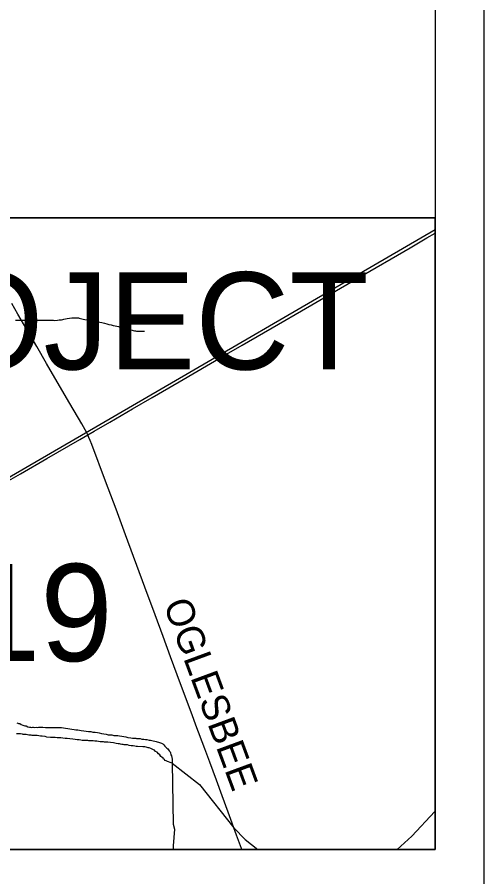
# Model space of a CAD drawing. Extents: x -19.5 to 44.1, y 0 to 22.
# Drawn here: x 8.541 to 9.5, y 17.841 to 19.61 of the extents above; entities that cross this region are included whole.
import ezdxf

# ---------------------------------------------------------------- set-up
doc = ezdxf.new("R2010")
doc.units = 0
for name, color, linetype in [('GM_X_County_Road', 7, 'Continuous'), ('GM_X_Minor_River', 7, 'Continuous'), ('GM_X_Township', 7, 'Continuous'), ('GM_X_Township_Road', 7, 'Continuous'), ('GM_X_Township_Road_Text', 7, 'Continuous'), ('SH_Data', 7, 'Continuous'), ('SH_Masking', 7, 'Continuous'), ('SH_Text', 7, 'Continuous')]:
    doc.layers.add(name, color=color, linetype=linetype)

msp = doc.modelspace()

# ---------------------------------------------------------------- linework, layer by layer
at = {"layer": 'GM_X_County_Road'}
for points in [[(8.6863, 18.7507), (8.6991, 18.7582), (8.7313, 18.777), (8.7781, 18.804), (8.8184, 18.8275), (8.8738, 18.8595), (8.9382, 18.8972), (8.9666, 18.9138), (9.0038, 18.9352), (9.0778, 18.9784), (9.1252, 19.0058), (9.1842, 19.0402), (9.2396, 19.0723), (9.3487, 19.1356), (9.383, 19.1556), (9.4, 19.1655)], [(8.5099, 18.6484), (8.5481, 18.6706), (8.6019, 18.7016), (8.6696, 18.7409), (8.6863, 18.7507)]]:
    msp.add_lwpolyline(points, dxfattribs=at)
at = {"layer": 'GM_X_Minor_River'}
for points in [[(8.5376, 18.9864), (8.5418, 18.9863), (8.5464, 18.9862), (8.5509, 18.9862), (8.5555, 18.9865), (8.5604, 18.9864), (8.5669, 18.9866), (8.5711, 18.9866), (8.5757, 18.9865), (8.5799, 18.9868), (8.5841, 18.9867), (8.5974, 18.9865), (8.6016, 18.9864), (8.6058, 18.9863), (8.6096, 18.9863), (8.6134, 18.9862), (8.616, 18.9862), (8.6183, 18.9861), (8.624, 18.9868), (8.6275, 18.9871), (8.6301, 18.9871), (8.6324, 18.9874), (8.6351, 18.9881), (8.637, 18.9885), (8.6401, 18.9892), (8.6439, 18.9899), (8.6485, 18.9906), (8.6531, 18.9912), (8.6569, 18.9912), (8.6599, 18.9915), (8.6622, 18.9915), (8.6641, 18.991), (8.6668, 18.991), (8.6687, 18.9906), (8.6713, 18.9902), (8.674, 18.9894), (8.677, 18.9889), (8.6804, 18.9881)], [(8.6804, 18.9881), (8.6842, 18.9873), (8.6876, 18.9868), (8.691, 18.986), (8.6948, 18.9852), (8.699, 18.9844), (8.715, 18.9814), (8.7203, 18.9802), (8.7252, 18.979), (8.7298, 18.9778), (8.7343, 18.9769), (8.7385, 18.9757), (8.7427, 18.9749), (8.7461, 18.9741), (8.7491, 18.9732), (8.7521, 18.9721), (8.7567, 18.9712), (8.7593, 18.9704), (8.7616, 18.97), (8.7635, 18.97), (8.7658, 18.9688), (8.7699, 18.9676), (8.7726, 18.9671), (8.7749, 18.9667), (8.7775, 18.9659), (8.7798, 18.9651), (8.7825, 18.9647), (8.7844, 18.9643), (8.7866, 18.9642), (8.7889, 18.9642), (8.792, 18.9642), (8.795, 18.9637), (8.7973, 18.9637), (8.7996, 18.9636), (8.8015, 18.9636), (8.8026, 18.9636)], [(8.5403, 18.1581), (8.5422, 18.1577), (8.5441, 18.1569), (8.5463, 18.1569), (8.5493, 18.1545), (8.5527, 18.1534), (8.5569, 18.1522), (8.5596, 18.1518), (8.5633, 18.1498), (8.5664, 18.1494), (8.5683, 18.149), (8.5701, 18.1486), (8.5724, 18.149), (8.5747, 18.1489), (8.5777, 18.1485), (8.5804, 18.1489), (8.5834, 18.1488), (8.5857, 18.1492), (8.5906, 18.1491), (8.5941, 18.1491), (8.5994, 18.1487), (8.6054, 18.1486), (8.6187, 18.1488), (8.6233, 18.1488), (8.6263, 18.1487), (8.632, 18.1487), (8.6362, 18.1475), (8.6407, 18.1471), (8.6452, 18.1466), (8.649, 18.1458), (8.6536, 18.145), (8.6581, 18.1446), (8.6619, 18.1438), (8.6657, 18.1434), (8.6695, 18.1429), (8.6729, 18.1425), (8.6782, 18.1417), (8.6828, 18.1409), (8.6877, 18.1405), (8.6922, 18.1404), (8.6968, 18.1392), (8.7013, 18.1388), (8.7059, 18.1383), (8.7097, 18.1372), (8.7142, 18.1364), (8.7191, 18.1355), (8.7237, 18.1347), (8.7282, 18.1335), (8.7331, 18.1331), (8.7354, 18.1331), (8.7396, 18.1323), (8.7434, 18.1322), (8.7479, 18.1318), (8.7513, 18.1314), (8.7559, 18.1306), (8.76, 18.1301), (8.7642, 18.129), (8.7687, 18.1281), (8.7744, 18.1273)], [(8.6685, 18.1228), (8.6647, 18.1229), (8.6606, 18.1237), (8.6556, 18.1245), (8.6492, 18.1253), (8.6439, 18.1257), (8.6397, 18.1262), (8.6348, 18.1266), (8.6306, 18.127), (8.6268, 18.1275), (8.623, 18.1275), (8.6193, 18.1279), (8.6162, 18.1276), (8.6132, 18.128), (8.6098, 18.128), (8.6018, 18.1289), (8.5984, 18.1301), (8.5927, 18.1309), (8.5889, 18.1309), (8.5859, 18.1313), (8.5825, 18.1318), (8.5798, 18.1318), (8.5772, 18.1322), (8.5741, 18.1322), (8.5719, 18.1323), (8.57, 18.1327), (8.5681, 18.1327), (8.5654, 18.1327), (8.562, 18.1335), (8.5597, 18.1339), (8.5567, 18.1343), (8.5537, 18.1344), (8.5518, 18.1348), (8.548, 18.1352), (8.5442, 18.1352), (8.5423, 18.1356), (8.5397, 18.1357)], [(8.7744, 18.1273), (8.7782, 18.1269), (8.7809, 18.1265), (8.7828, 18.1265), (8.7847, 18.1264), (8.7866, 18.126), (8.7888, 18.126), (8.7911, 18.1256), (8.7938, 18.1256), (8.7975, 18.1248), (8.8017, 18.1244), (8.8047, 18.1239), (8.8078, 18.1239), (8.8123, 18.1227), (8.8154, 18.1223), (8.8176, 18.1219), (8.8207, 18.1211), (8.8237, 18.1203), (8.8267, 18.1199), (8.829, 18.1191), (8.8316, 18.1183), (8.8335, 18.1175), (8.8354, 18.1171), (8.8377, 18.116), (8.8403, 18.1148), (8.8426, 18.1129), (8.8448, 18.1102), (8.8463, 18.1083), (8.8486, 18.1063), (8.8505, 18.1044), (8.8523, 18.1025), (8.8534, 18.1006), (8.8553, 18.0983), (8.8561, 18.0964), (8.8572, 18.0926), (8.8579, 18.0899), (8.859, 18.0865), (8.8593, 18.0834), (8.8597, 18.0811), (8.8597, 18.0785), (8.8596, 18.0751), (8.8577, 18.0759), (8.8555, 18.0763), (8.8524, 18.0778), (8.8498, 18.0786), (8.8475, 18.0798), (8.8449, 18.0809), (8.8434, 18.0832), (8.8415, 18.0836), (8.8408, 18.0855), (8.8385, 18.0875), (8.8366, 18.089), (8.834, 18.0925), (8.8317, 18.094), (8.8288, 18.0975), (8.8257, 18.0994), (8.8235, 18.1017), (8.8212, 18.1025), (8.8174, 18.1044), (8.8156, 18.1052), (8.8122, 18.1064), (8.8103, 18.1064), (8.8065, 18.108), (8.8031, 18.1088), (8.7993, 18.1088), (8.7887, 18.1097), (8.7856, 18.1097), (8.7826, 18.1101), (8.7792, 18.1106), (8.7754, 18.111), (8.7712, 18.1118), (8.7678, 18.1126), (8.7648, 18.113), (8.761, 18.113), (8.7587, 18.1134), (8.7561, 18.1138), (8.7534, 18.1143), (8.7512, 18.1147), (8.7485, 18.1151), (8.7443, 18.1155), (8.739, 18.1167), (8.733, 18.1179), (8.7273, 18.118), (8.7235, 18.118), (8.7205, 18.1184), (8.7182, 18.1188), (8.7152, 18.1192), (8.7117, 18.1193), (8.7083, 18.1197), (8.7045, 18.1201), (8.7007, 18.1202), (8.6973, 18.121), (8.6928, 18.1214), (8.6886, 18.1214), (8.686, 18.1215), (8.6829, 18.1215), (8.6799, 18.1219), (8.6772, 18.122), (8.675, 18.122), (8.6719, 18.1224), (8.6685, 18.1228)], [(8.8596, 18.0752), (8.916, 18.0312), (8.9861, 17.9422), (9.0099, 17.9178), (9.0359, 17.8973)], [(8.8596, 18.0751), (8.8615, 17.9494), (8.8644, 17.9391), (8.8615, 17.905), (8.862, 17.8973)], [(9.3221, 17.8973), (9.3522, 17.9249), (9.3993, 17.9757), (9.4, 17.9766)]]:
    msp.add_lwpolyline(points, dxfattribs=at)
at = {"layer": 'GM_X_Township'}
msp.add_lwpolyline([(9.4, 19.1723), (8.6813, 18.7543), (8.2198, 18.4859), (7.9056, 18.293), (7.7378, 18.1897), (7.7481, 18.1694), (7.371, 17.9444), (7.3983, 17.8973)], dxfattribs=at)
at = {"layer": 'GM_X_Township_Road'}
for points in [[(8.6863, 18.7507), (8.6856, 18.7522), (8.6835, 18.7564), (8.681, 18.761), (8.6743, 18.7729), (8.6494, 18.8152), (8.6284, 18.8512), (8.6016, 18.8974), (8.5814, 18.9324), (8.561, 18.9672), (8.5427, 18.999), (8.5299, 19.0211)], [(9.0027, 17.8973), (9.002, 17.8993), (8.9917, 17.9271), (8.975, 17.9741), (8.9624, 18.0079), (8.9506, 18.04), (8.9368, 18.0773), (8.9265, 18.1046), (8.9085, 18.1536), (8.9006, 18.1745), (8.877, 18.238), (8.8563, 18.294), (8.8408, 18.3359), (8.8245, 18.3802), (8.8034, 18.4374), (8.7637, 18.5446), (8.7442, 18.5977), (8.7227, 18.6553), (8.6944, 18.731), (8.6913, 18.739), (8.6887, 18.7454), (8.6873, 18.7486), (8.6863, 18.7507)]]:
    msp.add_lwpolyline(points, dxfattribs=at)
at = {"layer": 'SH_Data'}
for p, q in [((9.5, 21.3473), (9.5, 14.3473)), ((9.4, 21.2473), (9.4, 17.8973)), ((9.4, 17.8973), (2.6, 17.8973))]:
    msp.add_line(p, q, dxfattribs=at)
at = {"layer": 'SH_Masking'}
msp.add_lwpolyline([(6.7466, 19.1971), (9.4, 19.1971), (9.4, 17.8973), (6.7466, 17.8973)], close=True, dxfattribs=at)
at = {"layer": 'SH_Text'}
msp.add_lwpolyline([(6.7466, 17.8973), (9.4, 17.8973), (9.4, 19.1971), (6.7466, 19.1971)], close=True, dxfattribs=at)

# ---------------------------------------------------------------- texts
at = {"layer": 'GM_X_Township_Road_Text'}
msp.add_text('OGLESBEE', height=0.05682, rotation=290.2436, dxfattribs=at).set_placement((8.8411, 18.4023))
at = {"layer": 'SH_Text'}
for s, p in [('RESUME PROJECT', (6.797, 18.8851)), ('STA. 106+63.19', (6.797, 18.2851))]:
    msp.add_text(s, height=0.2, rotation=360, dxfattribs=at).set_placement(p)

doc.saveas('drawing.dxf')
